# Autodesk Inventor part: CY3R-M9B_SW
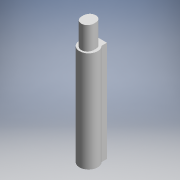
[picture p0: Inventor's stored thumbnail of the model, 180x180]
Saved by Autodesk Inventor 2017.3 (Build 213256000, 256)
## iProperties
Part Number: CY3R-M9B_SW
Material: Generic
Catalog Web Link: www.cadenas.de
Description: CY3R SW-Magnetically Coupled Rodless Cylinder Direct Mount Type
Vendor: SMC
Document SubType Name: Modeling
Designer: partserver
Manufacturer: SMC
Mass: 0.35879 g
Surface Area: 3.99853 cm^2
Volume: 0.35879 cm^3
Density: 1 g/cm^3
Appearance: PSOLRGB-255-255-255
Category: PARTsolutions
Company: SMC
Title: CY3R-M9B_SW
Author: Cadenas PARTsolutions
Comments: Magnetically Coupled Rodless Cylinder Direct Mount Type
PSOL_IDENT_0: {$CADENAS_DATA\23d-libs\smc_jp\actuator\rodless_cylinders\cy3\cy3r\parts\cy3r_sw.prj},173 {VTYP=3D},
PSOL_IDENT_1: {NB=CY3R-M9B_SW},{LINA=CY3R-M9B_SW},{NN=CY3R SW},{DATE=09.12.2020 02:54:07},{GEOMDATE=01.07.2020 05:
PSOL_IDENT_2: 54:21},{VERSION=},{LINEID=10},{WBVAR=AUTOSWITCH},{WBNUMERIC=}  {NB=CY3R-M9B_SW},{LINA=CY3R-M9B_SW},{
PSOL_IDENT_3: KT=DUMMY},{AUTOSWITCH=-M9B}
NB: CY3R-M9B_SW
NN: CY3R SW
NT: Magnetically Coupled Rodless Cylinder Direct Mount Type
NBSYN: CY3R$AUTOSWITCH._SW
LINA: CY3R-M9B_SW
CATALOG: SMC (JP
AUTOSWITCH: M9B Solid state-General-Grommet-Indicator light:Yes-2 wire-In line
SUPPLIER: SMC
ARTICLENO: CY3R-M9B_SW
BOMINFO: CY3R-M9B_SW
CREATOR: CADENAS GmbH
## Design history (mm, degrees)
sketch "Sketch_1"
  geometry: L1 (1.4, 1.428)-(1.4, 2.6); L2 (1.4, 2.6)-(-1.4, 2.6); L3 (-1.4, 2.6)-(-1.4, 1.428); A1 r 2 centre (0, 0) between (-1.4, 1.428) and (1.4, 1.428)
  constraints: 6 end point, 2 point on circle, 1 centre point
extrude "Extrusion1" join sketch "Sketch_1" distance "d0" = 22; taper "d1" = 0 deg
sketch "Sketch_2"
  geometry: L1 (-1.35, 0.25)-(-1.35, -0.25); L2 (1.35, -0.25)-(1.35, 0.25); A1 r 1.35 centre (0, -0.25) between (-1.35, -0.25) and (1.35, -0.25); A2 r 1.35 centre (0, 0.25) between (1.35, 0.25) and (-1.35, 0.25)
  constraints: 4 end point, 4 point on circle, 2 centre point
extrude "Extrusion2" join sketch "Sketch_2" distance "d2" = 27; taper "d3" = 0 deg
sketch "Sketch3"
  geometry: 1 further point
hole "Hole1" sketch "Sketch3" at (1.4, 2) diameter "d4" = 2.5; stored, may be unused: countersink angle "d8" = 90 deg, drill point angle "d10" = 0 deg; dims "d5" = 6, "d6" = 4, "d7" = 2, "d9" = 0.2
node "SW_CT_XY"
node "SW_CT_YZ"
node "SW_CT_ZX"
node "SW_CT_X"
node "SW_CT_Y"
node "SW_CT_Z"
node "SW_CT_Center"
body "Solid1"
other parameters: "d11" = 0
